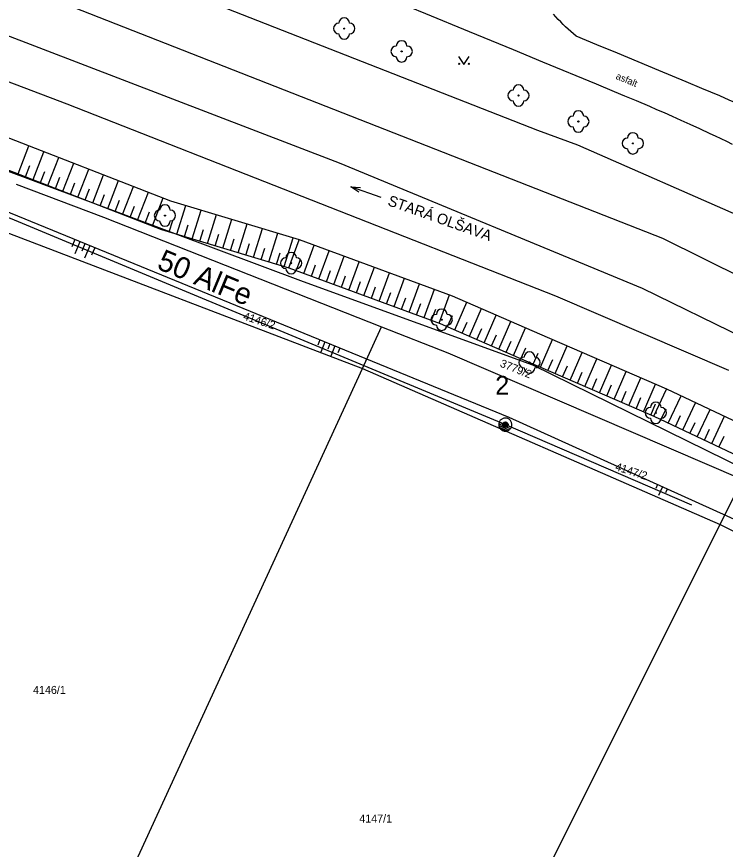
# Model space of a CAD drawing. Extents: x -540150 to -533593, y -1185082 to -1180066.
# Drawn here: x -536148.4 to -536082.1, y -1184596.8 to -1184518.8 of the extents above; entities that cross this region are included whole.
import ezdxf

# ---------------------------------------------------------------- set-up
doc = ezdxf.new("R2010")
doc.units = 0
for name, color, linetype in [('KN_HRAN_K_Ú', 7, 'Continuous'), ('KN_HRAN_PARCEL', 7, 'Continuous'), ('KN_PARC_Č', 7, 'Continuous'), ('Vrstva 10', 7, 'Continuous'), ('Vrstva 13', 7, 'Continuous'), ('Vrstva 14', 7, 'Continuous'), ('Vrstva 15', 7, 'Continuous'), ('Vrstva 2', 7, 'Continuous'), ('Vrstva 22', 7, 'Continuous'), ('Vrstva 25', 7, 'Continuous'), ('Vrstva 36', 7, 'Continuous'), ('Vrstva 40', 7, 'Continuous'), ('Vrstva 45', 7, 'Continuous'), ('Vrstva 52', 7, 'Continuous'), ('Vrstva 53', 7, 'Continuous'), ('Vrstva 7', 7, 'Continuous')]:
    doc.layers.add(name, color=color, linetype=linetype)

# ---------------------------------------------------------------- blocks, each defined once
blk = doc.blocks.new('VN440')
at = {"layer": 'Vrstva 2'}
for points in [[(1.22, 0), (1.21, 0.13), (1.19, 0.25), (1.16, 0.38), (1.11, 0.5), (1.05, 0.61), (0.98, 0.72), (0.9, 0.82), (0.81, 0.91), (0.71, 0.99), (0.6, 1.06), (0.49, 1.12), (0.37, 1.16), (0.25, 1.2), (0.12, 1.22), (-0.01, 1.22), (-0.14, 1.22), (-0.26, 1.2), (-0.39, 1.16), (-0.51, 1.12), (-0.62, 1.06), (-0.73, 0.99), (-0.83, 0.91), (-0.92, 0.82), (-1, 0.72), (-1.07, 0.61), (-1.13, 0.5), (-1.18, 0.38), (-1.21, 0.25), (-1.23, 0.13), (-1.24, 0), (-1.23, -0.13), (-1.21, -0.26), (-1.18, -0.38), (-1.13, -0.5), (-1.07, -0.62), (-1, -0.73), (-0.92, -0.83), (-0.83, -0.92), (-0.73, -1), (-0.62, -1.07), (-0.51, -1.13), (-0.39, -1.17), (-0.26, -1.2), (-0.14, -1.23), (-0.01, -1.23), (0.12, -1.23), (0.25, -1.2), (0.37, -1.17), (0.49, -1.13), (0.6, -1.07), (0.71, -1), (0.81, -0.92), (0.9, -0.83), (0.98, -0.73), (1.05, -0.62), (1.11, -0.5), (1.16, -0.38), (1.19, -0.26), (1.21, -0.13), (1.22, 0)], [(-1.24, 0), (1.22, 0)], [(-1.18, -0.34), (1.1, -0.34)], [(-1.01, -0.63), (0.97, -0.63)], [(-0.74, -0.92), (0.68, -0.92)]]:
    blk.add_lwpolyline(points, dxfattribs=at)

msp = doc.modelspace()

# ---------------------------------------------------------------- linework, layer by layer
at = {"layer": 'KN_HRAN_K_Ú'}
for p, q in [((-536165.051, -1184518.865), (-536143.731, -1184526.945)), ((-536143.731, -1184526.945), (-536097.971, -1184544.935)), ((-536097.971, -1184544.935), (-536081.751, -1184551.905))]:
    msp.add_line(p, q, dxfattribs=at)
at = {"layer": 'KN_HRAN_PARCEL'}
for p, q in [((-536118.191, -1184532.505), (-536174.061, -1184511.065)), ((-536087.901, -1184539.565), (-536147.161, -1184516.325)), ((-536184.081, -1184520.235), (-536121.601, -1184543.605)), ((-536089.811, -1184544.255), (-536118.191, -1184532.505)), ((-536148.481, -1184534.475), (-536140.301, -1184537.575)), ((-536140.301, -1184537.575), (-536114.251, -1184547.845)), ((-536150.191, -1184538.715), (-536116.051, -1184551.765)), ((-536053.711, -1184556.685), (-536087.901, -1184539.565)), ((-536121.601, -1184543.605), (-536100.101, -1184551.425)), ((-536058.921, -1184559.435), (-536089.811, -1184544.255)), ((-536116.051, -1184551.765), (-536114.251, -1184547.845)), ((-536114.251, -1184547.845), (-536108.031, -1184550.295)), ((-536108.031, -1184550.295), (-536080.431, -1184562.155)), ((-536147.031, -1184619.185), (-536116.051, -1184551.765)), ((-536116.051, -1184551.765), (-536082.541, -1184566.365)), ((-536100.101, -1184551.425), (-536065.341, -1184568.525)), ((-536082.541, -1184566.365), (-536080.431, -1184562.155)), ((-536115.491, -1184632.165), (-536082.541, -1184566.365)), ((-536082.541, -1184566.365), (-536062.011, -1184576.815))]:
    msp.add_line(p, q, dxfattribs=at)
at = {"layer": 'Vrstva 10'}
for p, q in [((-536094.084, -1184521.415), (-536096.011, -1184520.605)), ((-536094.114, -1184525.128), (-536099.161, -1184523.045)), ((-536102.301, -1184556.335), (-536158.141, -1184533.475)), ((-536066.411, -1184572.605), (-536102.301, -1184556.335))]:
    msp.add_line(p, q, dxfattribs=at)
for points in [[(-536106.01, -1184520.211), (-536110.121, -1184518.515), (-536111.646, -1184517.89), (-536113.078, -1184517.31), (-536114.422, -1184516.77)], [(-536096.011, -1184520.605), (-536096.268, -1184520.401), (-536096.521, -1184520.19), (-536096.768, -1184519.973), (-536097.01, -1184519.75), (-536097.247, -1184519.522), (-536097.477, -1184519.288), (-536097.702, -1184519.048), (-536097.921, -1184518.803), (-536098.135, -1184518.552)], [(-536099.161, -1184523.045), (-536101.9, -1184521.91), (-536106.01, -1184520.211)], [(-536085.72, -1184524.896), (-536088.293, -1184523.824), (-536092.155, -1184522.22), (-536094.084, -1184521.415)], [(-536090.379, -1184526.688), (-536091.474, -1184526.227), (-536092.433, -1184525.825), (-536094.114, -1184525.128)], [(-536077.491, -1184528.435), (-536078.64, -1184527.925), (-536079.718, -1184527.453), (-536080.731, -1184527.013), (-536081.683, -1184526.604), (-536082.575, -1184526.222), (-536084.251, -1184525.513), (-536085.72, -1184524.896)], [(-536081.382, -1184530.766), (-536081.927, -1184530.499), (-536082.455, -1184530.243), (-536082.968, -1184529.997), (-536083.466, -1184529.761), (-536084.434, -1184529.31), (-536085.343, -1184528.893), (-536086.198, -1184528.507), (-536087.001, -1184528.149), (-536087.756, -1184527.817), (-536088.464, -1184527.509), (-536089.129, -1184527.222), (-536090.379, -1184526.688)]]:
    msp.add_lwpolyline(points, dxfattribs=at)
at = {"layer": 'Vrstva 14'}
for p, q in [((-536173.912, -1184520.571), (-536134.024, -1184536.04)), ((-536174.871, -1184523.215), (-536134.851, -1184538.735)), ((-536134.024, -1184536.04), (-536121.982, -1184539.68)), ((-536134.851, -1184538.735), (-536122.941, -1184542.335)), ((-536121.982, -1184539.68), (-536107.642, -1184544.939)), ((-536122.941, -1184542.335), (-536108.761, -1184547.535)), ((-536107.642, -1184544.939), (-536099.465, -1184548.513)), ((-536108.761, -1184547.535), (-536100.731, -1184551.045)), ((-536099.465, -1184548.513), (-536087.564, -1184553.673)), ((-536100.731, -1184551.045), (-536088.761, -1184556.235)), ((-536087.564, -1184553.673), (-536074.747, -1184559.712)), ((-536088.761, -1184556.235), (-536076.111, -1184562.195))]:
    msp.add_line(p, q, dxfattribs=at)
at = {"layer": 'Vrstva 15'}
for p, q in [((-536148.299, -1184533.52), (-536147.282, -1184530.898)), ((-536146.901, -1184534.062), (-536145.884, -1184531.441)), ((-536145.502, -1184534.604), (-536144.485, -1184531.983)), ((-536144.104, -1184535.147), (-536143.087, -1184532.525)), ((-536147.6, -1184533.791), (-536147.193, -1184532.742)), ((-536146.201, -1184534.333), (-536145.795, -1184533.285)), ((-536142.705, -1184535.689), (-536141.688, -1184533.068)), ((-536144.803, -1184534.876), (-536144.396, -1184533.827)), ((-536141.307, -1184536.231), (-536140.29, -1184533.61)), ((-536143.404, -1184535.418), (-536142.998, -1184534.369)), ((-536142.006, -1184535.96), (-536141.599, -1184534.912)), ((-536139.908, -1184536.774), (-536138.891, -1184534.152)), ((-536138.51, -1184537.316), (-536137.493, -1184534.695)), ((-536140.607, -1184536.503), (-536140.201, -1184535.454)), ((-536137.111, -1184537.859), (-536136.094, -1184535.237)), ((-536139.209, -1184537.045), (-536138.802, -1184535.996)), ((-536135.712, -1184538.401), (-536134.696, -1184535.779)), ((-536133.415, -1184539.169), (-536132.599, -1184536.471)), ((-536137.81, -1184537.587), (-536137.404, -1184536.539)), ((-536136.412, -1184538.13), (-536136.005, -1184537.081)), ((-536131.979, -1184539.603), (-536131.163, -1184536.905)), ((-536134.133, -1184538.952), (-536133.807, -1184537.873)), ((-536130.543, -1184540.037), (-536129.728, -1184537.339)), ((-536129.108, -1184540.471), (-536128.292, -1184537.773)), ((-536132.697, -1184539.386), (-536132.371, -1184538.307)), ((-536131.261, -1184539.82), (-536130.935, -1184538.741)), ((-536127.672, -1184540.905), (-536126.856, -1184538.207)), ((-536126.236, -1184541.339), (-536125.42, -1184538.641)), ((-536129.826, -1184540.254), (-536129.499, -1184539.175)), ((-536128.39, -1184540.688), (-536128.064, -1184539.609)), ((-536124.8, -1184541.773), (-536123.984, -1184539.075)), ((-536123.364, -1184542.207), (-536122.548, -1184539.509)), ((-536142.975, -1184539.684), (-536143.258, -1184540.369)), ((-536142.512, -1184539.873), (-536142.988, -1184541.022)), ((-536142.049, -1184540.063), (-536142.335, -1184540.752)), ((-536141.586, -1184540.252), (-536142.064, -1184541.405)), ((-536126.954, -1184541.122), (-536126.628, -1184540.043)), ((-536122.941, -1184542.335), (-536121.969, -1184539.685)), ((-536121.533, -1184542.851), (-536120.561, -1184540.201)), ((-536141.123, -1184540.442), (-536141.411, -1184541.135)), ((-536125.518, -1184541.556), (-536125.192, -1184540.477)), ((-536124.082, -1184541.99), (-536123.756, -1184540.911)), ((-536120.124, -1184543.368), (-536119.153, -1184540.718)), ((-536122.237, -1184542.593), (-536121.848, -1184541.533)), ((-536118.716, -1184543.884), (-536117.745, -1184541.234)), ((-536117.308, -1184544.401), (-536116.336, -1184541.751)), ((-536120.829, -1184543.11), (-536120.44, -1184542.05)), ((-536119.42, -1184543.626), (-536119.032, -1184542.566)), ((-536115.9, -1184544.917), (-536114.928, -1184542.267)), ((-536118.012, -1184544.143), (-536117.623, -1184543.082)), ((-536114.491, -1184545.434), (-536113.52, -1184542.783)), ((-536113.083, -1184545.95), (-536112.111, -1184543.3)), ((-536116.604, -1184544.659), (-536116.215, -1184543.599)), ((-536115.195, -1184545.175), (-536114.807, -1184544.115)), ((-536111.675, -1184546.467), (-536110.703, -1184543.817)), ((-536113.787, -1184545.692), (-536113.398, -1184544.632)), ((-536110.266, -1184546.983), (-536109.295, -1184544.333)), ((-536108.858, -1184547.499), (-536107.887, -1184544.849)), ((-536112.379, -1184546.208), (-536111.99, -1184545.148)), ((-536110.971, -1184546.725), (-536110.582, -1184545.665)), ((-536107.387, -1184548.136), (-536106.254, -1184545.546)), ((-536109.562, -1184547.241), (-536109.174, -1184546.181)), ((-536106.012, -1184548.737), (-536104.88, -1184546.146)), ((-536108.074, -1184547.835), (-536107.621, -1184546.799)), ((-536106.699, -1184548.436), (-536106.247, -1184547.4)), ((-536104.638, -1184549.337), (-536103.505, -1184546.747)), ((-536103.263, -1184549.938), (-536102.131, -1184547.348)), ((-536105.325, -1184549.037), (-536104.872, -1184548.001)), ((-536101.889, -1184550.539), (-536100.756, -1184547.949)), ((-536103.95, -1184549.638), (-536103.498, -1184548.602)), ((-536120.028, -1184549.078), (-536120.221, -1184549.576)), ((-536119.565, -1184549.267), (-536119.936, -1184550.223)), ((-536119.102, -1184549.457), (-536119.289, -1184549.938)), ((-536118.639, -1184549.646), (-536119.004, -1184550.585)), ((-536102.576, -1184550.239), (-536102.123, -1184549.202)), ((-536099.355, -1184551.642), (-536098.231, -1184549.048)), ((-536097.979, -1184552.238), (-536096.854, -1184549.645)), ((-536118.177, -1184549.836), (-536118.357, -1184550.3)), ((-536101.202, -1184550.839), (-536100.749, -1184549.803)), ((-536100.043, -1184551.343), (-536099.593, -1184550.306)), ((-536096.602, -1184552.835), (-536095.478, -1184550.242)), ((-536098.667, -1184551.94), (-536098.217, -1184550.903)), ((-536095.226, -1184553.432), (-536094.101, -1184550.838)), ((-536097.29, -1184552.537), (-536096.841, -1184551.499)), ((-536093.85, -1184554.029), (-536092.726, -1184551.435)), ((-536092.474, -1184554.625), (-536091.35, -1184552.032)), ((-536095.914, -1184553.133), (-536095.464, -1184552.096)), ((-536094.538, -1184553.73), (-536094.088, -1184552.693)), ((-536091.098, -1184555.222), (-536089.973, -1184552.628)), ((-536093.162, -1184554.327), (-536092.712, -1184553.289)), ((-536089.721, -1184555.819), (-536088.597, -1184553.225)), ((-536091.786, -1184554.924), (-536091.336, -1184553.886)), ((-536088.761, -1184556.235), (-536087.556, -1184553.677)), ((-536087.404, -1184556.874), (-536086.199, -1184554.316)), ((-536090.409, -1184555.52), (-536089.959, -1184554.483)), ((-536089.033, -1184556.117), (-536088.583, -1184555.08)), ((-536086.047, -1184557.514), (-536084.842, -1184554.956)), ((-536088.083, -1184556.555), (-536087.6, -1184555.531)), ((-536084.69, -1184558.153), (-536083.485, -1184555.595)), ((-536086.726, -1184557.194), (-536086.243, -1184556.171)), ((-536083.333, -1184558.792), (-536082.128, -1184556.234)), ((-536085.369, -1184557.833), (-536084.887, -1184556.81)), ((-536084.012, -1184558.473), (-536083.53, -1184557.449)), ((-536082.655, -1184559.112), (-536082.173, -1184558.089)), ((-536088.407, -1184562.633), (-536088.571, -1184562.989)), ((-536087.952, -1184562.84), (-536088.327, -1184563.653)), ((-536087.496, -1184563.046), (-536087.663, -1184563.408))]:
    msp.add_line(p, q, dxfattribs=at)
at = {"layer": 'Vrstva 22'}
for centre in [(-536117.751, -1184519.905), (-536112.371, -1184522.045), (-536101.431, -1184526.175), (-536095.821, -1184528.615), (-536090.711, -1184530.665), (-536134.541, -1184537.425), (-536122.717, -1184541.888), (-536108.623, -1184547.186), (-536100.399, -1184551.19), (-536088.569, -1184555.913)]:
    msp.add_circle(centre, 0.05, dxfattribs=at)
for centre, start, end in [((-536117.751, -1184519.405), 0, 180), ((-536118.251, -1184519.905), 90, 270), ((-536117.251, -1184519.905), 270, 90), ((-536117.751, -1184520.405), 180, 0), ((-536112.871, -1184522.045), 90, 270), ((-536112.371, -1184521.545), 0, 180), ((-536111.871, -1184522.045), 270, 90), ((-536112.371, -1184522.545), 180, 0), ((-536101.431, -1184525.675), 0, 180), ((-536101.931, -1184526.175), 90, 270), ((-536100.931, -1184526.175), 270, 90), ((-536101.431, -1184526.675), 180, 0), ((-536095.821, -1184528.115), 0, 180), ((-536096.321, -1184528.615), 90, 270), ((-536095.321, -1184528.615), 270, 90), ((-536095.821, -1184529.115), 180, 0), ((-536091.211, -1184530.665), 90, 270), ((-536090.711, -1184530.165), 0, 180), ((-536090.211, -1184530.665), 270, 90), ((-536090.711, -1184531.165), 180, 0), ((-536134.541, -1184536.925), 0, 180), ((-536135.041, -1184537.425), 90, 270), ((-536134.041, -1184537.425), 270, 90), ((-536134.541, -1184537.925), 180, 0), ((-536122.717, -1184541.388), 0, 180), ((-536123.217, -1184541.888), 90, 270), ((-536122.217, -1184541.888), 270, 90), ((-536122.717, -1184542.388), 180, 0), ((-536108.623, -1184546.686), 0, 180), ((-536109.123, -1184547.186), 90, 270), ((-536108.123, -1184547.186), 270, 90), ((-536108.623, -1184547.686), 180, 0), ((-536100.399, -1184550.69), 0, 180), ((-536100.899, -1184551.19), 90, 270), ((-536099.899, -1184551.19), 270, 90), ((-536100.399, -1184551.69), 180, 0), ((-536088.569, -1184555.413), 0, 180), ((-536089.069, -1184555.913), 90, 270), ((-536088.069, -1184555.913), 270, 90), ((-536088.569, -1184556.413), 180, 0)]:
    msp.add_arc(centre, 0.5, start, end, dxfattribs=at)
at = {"layer": 'Vrstva 25'}
for radius in [0.25, 0.2, 0.15, 0.1, 0.05]:
    msp.add_circle((-536102.658, -1184557.011), radius, dxfattribs=at)
at = {"layer": 'Vrstva 36'}
msp.add_lwpolyline([(-536107.037, -1184522.508), (-536106.537, -1184523.258), (-536106.037, -1184522.508)], dxfattribs=at)
for centre in [(-536106.988, -1184523.208), (-536106.088, -1184523.208)]:
    msp.add_circle(centre, 0.05, dxfattribs=at)
at = {"layer": 'Vrstva 45'}
msp.add_line((-536114.299, -1184535.727), (-536117.127, -1184534.727), dxfattribs=at)
msp.add_lwpolyline([(-536116.378, -1184535.236), (-536117.127, -1184534.727), (-536116.224, -1184534.802)], dxfattribs=at)
at = {"layer": 'Vrstva 52'}
msp.add_lwpolyline([(-536158.226, -1184533.85), (-536102.657, -1184557.011), (-536085.232, -1184564.516)], dxfattribs=at)
at = {"layer": 'Vrstva 7'}
for p, q in [((-536095.881, -1184530.825), (-536099.631, -1184529.465)), ((-536074.121, -1184540.395), (-536095.881, -1184530.825))]:
    msp.add_line(p, q, dxfattribs=at)
msp.add_lwpolyline([(-536099.631, -1184529.465), (-536130.301, -1184517.435)], dxfattribs=at)

# ---------------------------------------------------------------- block references
at = {"layer": 'Vrstva 13', "xscale": 0.5, "yscale": 0.5000000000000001, "rotation": -22.62591945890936}
msp.add_blockref('VN440', (-536102.658, -1184557.011), dxfattribs=at)

# ---------------------------------------------------------------- texts
at = {"layer": 'KN_PARC_Č'}
for s, rotation, p in [('4146/2', 342, (-536127.268, -1184547.151)), ('3779/2', 338.2639, (-536103.222, -1184551.561)), ('4147/2', 342, (-536092.426, -1184561.258))]:
    msp.add_text(s, height=0.75, rotation=rotation, dxfattribs=at).set_placement(p)
for s, p in [('4146/1', (-536146.9, -1184582.245)), ('4147/1', (-536116.34, -1184594.295))]:
    msp.add_text(s, height=0.75, dxfattribs=at).set_placement(p)
at = {"layer": 'Vrstva 14'}
msp.add_text('2', height=1.75, dxfattribs=at).set_placement((-536103.602, -1184554.197))
at = {"layer": 'Vrstva 40'}
msp.add_text('asfalt', height=0.65, rotation=337.46643, dxfattribs=at).set_placement((-536092.37, -1184524.598))
at = {"layer": 'Vrstva 45'}
msp.add_text('STARÁ OLŠAVA', height=1, rotation=340.53243, dxfattribs=at).set_placement((-536113.752, -1184536.439))
at = {"layer": 'Vrstva 53'}
msp.add_text('50 AlFe', height=2, rotation=337.374, dxfattribs=at).set_placement((-536135.399, -1184542.371))

doc.saveas('drawing.dxf')
